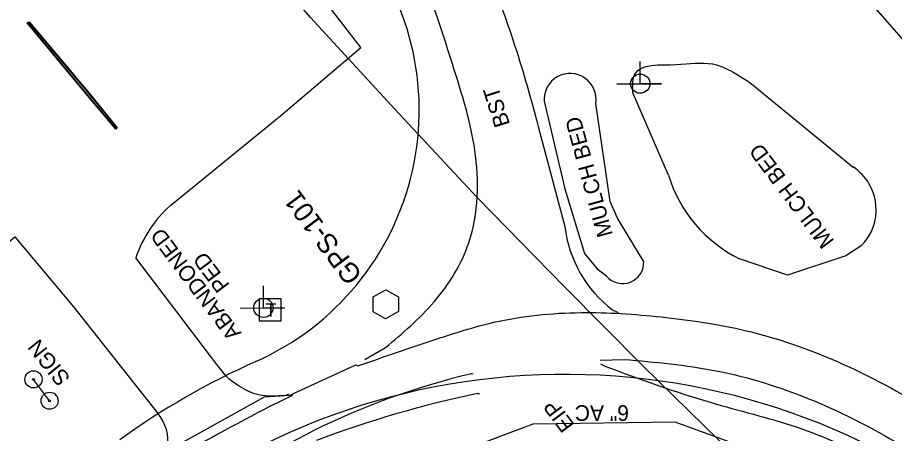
# Model space of a CAD drawing. Extents: x 1263837 to 1268319, y 770628 to 773628.
# Drawn here: x 1266190 to 1266413.1, y 772410.1 to 772515.9 of the extents above; entities that cross this region are included whole.
import ezdxf

# ---------------------------------------------------------------- set-up
doc = ezdxf.new("R2010")
doc.units = 0
for name, color, linetype in [('CTL Primary Horizontal and Vertical CELL', 7, 'Continuous'), ('CTL Primary Horizontal and Vertical Text', 7, 'Continuous'), ('Exist Other Culture Area Outline', 7, 'Continuous'), ('Exist Other Culture Area Outline Text', 7, 'Continuous'), ('Exist Other Culture Sign', 7, 'Continuous'), ('Exist Other Culture Sign Text', 7, 'Continuous'), ('Exist Property Iron Pin Text', 7, 'Continuous'), ('Exist Roads EOP Other', 7, 'Continuous'), ('Exist Roads EOP Text', 7, 'Continuous'), ('Exist Utilities Gas UG Line SUE LOS B', 7, 'Continuous'), ('Exist Utilities Power Joint Use Telephone CELL', 7, 'Continuous'), ('Exist Utilities Telephone Pedestal CELL', 7, 'Continuous'), ('Exist Utilities Telephone Pedestal Text', 7, 'Continuous'), ('Exist Utilities Water UG Line SUE LOS B', 7, 'Continuous'), ('Exist Utilities Water UG Line SUE LOS B Text', 7, 'Continuous'), ('Prop Horizontal Alignment', 7, 'Continuous'), ('Prop SS Fill Text', 7, 'Continuous'), ('Prop SS Transition Line', 7, 'Continuous'), ('Scratch_Level_2', 7, 'Continuous')]:
    doc.layers.add(name, color=color, linetype=linetype)

# ---------------------------------------------------------------- blocks, each defined once
blk = doc.blocks.new('EXIST UTILITIES POWER JOINT USE TELEPHONE')
at = {"layer": 'Exist Utilities Power Joint Use Telephone CELL'}
blk.add_line((0, 0), (0, 0), dxfattribs=at)
blk.add_lwpolyline([(-0.1188, 0), (0.108, -0.0008), (0, -0.0004), (0, 0.1125)], dxfattribs=at)
blk.add_circle((0, 0.0001), 0.049, dxfattribs=at)
blk = doc.blocks.new('EXIST UTILITIES TELEPHONE PEDESTAL')
at = {"layer": 'Exist Utilities Telephone Pedestal CELL'}
blk.add_line((0, 0), (0, 0), dxfattribs=at)
blk.add_lwpolyline([(-0.0545, -0.0565), (0.0574, -0.0565), (0.0574, 0.0554), (-0.0545, 0.0554), (-0.0545, -0.0565)], dxfattribs=at)
blk.add_text('T', height=0.0684, dxfattribs=at).set_placement((-0.0226, -0.0343))
blk = doc.blocks.new('CTL PRIMARY HORIZONTAL AND VERTICAL')
at = {"layer": 'CTL Primary Horizontal and Vertical CELL'}
blk.add_line((0, 0), (0, 0), dxfattribs=at)
blk.add_lwpolyline([(-0.0646, 0.0374), (0.0004, 0.0737), (0.0654, 0.0379), (0.0644, -0.0366), (-0.0006, -0.0743), (-0.0646, -0.0381)], close=True, dxfattribs=at)

msp = doc.modelspace()

# ---------------------------------------------------------------- linework, layer by layer
at = {"layer": 'Exist Other Culture Area Outline'}
for p, q in [((1266376.78, 772498.99), (1266402.61, 772477.85)), ((1266355.61, 772475.79), (1266346.58, 772496.72)), ((1266385.86, 772450.36), (1266373.65, 772454.51)), ((1266337.48, 772451.92), (1266339.86, 772450.14))]:
    msp.add_line(p, q, dxfattribs=at)
for points in [[(1266324.02, 772494.58), (1266329.26, 772472.26), (1266334.27, 772455.86), (1266337.48, 772451.92)], [(1266349.3, 772453.94), (1266342.64, 772464.83), (1266340.75, 772469.12), (1266337.12, 772493.99)], [(1266404.61, 772457.77), (1266400.71, 772455.26), (1266385.86, 772450.36)]]:
    msp.add_lwpolyline(points, dxfattribs=at)
for centre, major_axis, ratio, start_param, end_param in [((1266330.61, 772495.04), (-1.74, 6.39), 0.995965, 4.288081, 7.657894), ((1266395.46, 772467.08), (-10.22, 8.12), 0.990932, 3.017808, 4.796693), ((1266389.03, 772485.66), (26.79, -22.79), 0.986857, 4.139678, 4.955444), ((1266343.98, 772453.54), (4.6, -2.73), 0.999091, 4.368627, 6.893524)]:
    msp.add_ellipse(centre, major_axis=major_axis, ratio=ratio, start_param=start_param, end_param=end_param, dxfattribs=at)
msp.add_spline([(1266346.58, 772496.72), (1266347.13, 772501.58), (1266357.47, 772503.91), (1266366.8, 772504.06), (1266376.78, 772498.99)], degree=3, dxfattribs=at)
at = {"layer": 'Exist Other Culture Sign'}
msp.add_line((1266198.2, 772418.41), (1266194.11, 772423.85), dxfattribs=at)
for centre, radius in [((1266194.11, 772423.85), 2.18), ((1266194.11, 772423.85), 0.24), ((1266198.2, 772418.41), 2.18), ((1266198.2, 772418.41), 0.24)]:
    msp.add_circle(centre, radius, dxfattribs=at)
at = {"layer": 'Exist Roads EOP Other'}
msp.add_lwpolyline([(1266192.91, 772514.69), (1266207.85, 772496.92), (1266215.26, 772487.95), (1266215.01, 772487.7), (1266207.44, 772496.7), (1266192.76, 772514.42), (1266192.91, 772514.69)], dxfattribs=at)
at = {"layer": 'Exist Utilities Gas UG Line SUE LOS B'}
msp.add_lwpolyline([(1266634.89, 772116.41), (1266617.88, 772134.08), (1266593.74, 772162.87), (1266570.59, 772187.5), (1266552.2, 772208.93), (1266533.9, 772229.88), (1266520.79, 772243.67), (1266506.09, 772258.4), (1266476.3, 772293.88), (1266450.61, 772322.46), (1266432.17, 772342.72), (1266403.52, 772374.96), (1266376.24, 772400.79), (1266349.14, 772427.18), (1266329.27, 772447.31), (1266306.87, 772470.18), (1266286, 772492.58), (1266264.53, 772515.83), (1266241.63, 772542.64), (1266214.18, 772573.35), (1266190.07, 772598.41)], dxfattribs=at)
at = {"layer": 'Exist Utilities Water UG Line SUE LOS B'}
msp.add_lwpolyline([(1266813.73, 772072.54), (1266793.78, 772088.05), (1266755.27, 772103.69), (1266718.33, 772109.44), (1266678.54, 772111.01), (1266653.19, 772143.96), (1266605.92, 772197.31), (1266538.03, 772271.69), (1266479.88, 772335.62), (1266421.78, 772389.51), (1266357.3, 772412.97), (1266321.15, 772412.43), (1266255.77, 772387.79), (1266212.97, 772357.83), (1266212.08, 772352.35), (1266208.85, 772350.26), (1266194.96, 772350.29), (1266178.01, 772373.6), (1266155.19, 772357.9), (1266088.3, 772309.2), (1266057.71, 772286.98)], dxfattribs=at)
at = {"layer": 'Prop Horizontal Alignment'}
for centre, radius, start, end in [((1275094.23, 780056.99), 11329.16, 216.983333, 223.309327), ((1266222.23, 772492.36), 70, 293.9809, 40.4523), ((1266329.37, 772251.49), 193.62, 113.9809, 125.8167)]:
    msp.add_arc(centre, radius, start, end, dxfattribs=at)
at = {"layer": 'Prop SS Fill Text'}
for p, q in [((1266323.19, 772485.61), (1266329.27, 772462.71)), ((1266240.76, 772427.65), (1266220.16, 772454.78)), ((1266341.39, 772441.5), (1266342.84, 772440.85)), ((1266278.42, 772428.88), (1266283.64, 772431.92)), ((1266258.93, 772420.09), (1266258.29, 772419.74))]:
    msp.add_line(p, q, dxfattribs=at)
for points in [[(1266317.66, 772623.29), (1266342.19, 772594.53), (1266368.84, 772563.85), (1266396.95, 772531.19), (1266423.69, 772500.53), (1266451.34, 772469.08), (1266485.04, 772430.62), (1266513.92, 772398.56), (1266542.2, 772366.82), (1266568.73, 772337.14), (1266597.4, 772305.79), (1266627.45, 772273.2), (1266656.25, 772242.01), (1266683.72, 772211.17), (1266699.81, 772190.48)], [(1266229.02, 772468.13), (1266256.91, 772490.84), (1266277.4, 772508.24), (1266257.18, 772534.45), (1266234.23, 772562.55), (1266211.6, 772588.72), (1266200.28, 772601.91), (1266164.52, 772601.03), (1266130.88, 772600.07), (1266121.81, 772599.68), (1266117.21, 772604.39), (1266093.43, 772584.35), (1266064.08, 772559.94), (1266085.39, 772534.82), (1266055.13, 772509.93), (1266076.92, 772483.37), (1266101.03, 772454.47), (1266125.49, 772425.14), (1266134.49, 772414.39), (1266146.49, 772424.38), (1266164.67, 772402.08), (1266177.9, 772383.87)], [(1266193.03, 772514.81), (1266207.97, 772497.01), (1266215.43, 772487.83), (1266215.06, 772487.49), (1266207.41, 772496.55), (1266192.47, 772514.55), (1266193.03, 772514.81)], [(1266195.78, 772393.53), (1266179.19, 772413.75), (1266161.27, 772436.42), (1266189.4, 772460.06), (1266204.32, 772442.33), (1266225.79, 772415.07)], [(1266025.59, 772259.29), (1266057.53, 772282.19), (1266090.3, 772305.71), (1266122.01, 772329.02), (1266153.74, 772351.9), (1266173.76, 772367.02), (1266177.28, 772371.96), (1266201.03, 772388.23), (1266203.83, 772389.82), (1266209.58, 772391.53), (1266225.6, 772401.19), (1266228.25, 772405.78), (1266239.93, 772412.21), (1266252.84, 772419.39), (1266259.27, 772419.81), (1266276.13, 772427.55), (1266276.62, 772427.29)]]:
    msp.add_lwpolyline(points, dxfattribs=at)
for centre, major_axis, ratio, start_param, end_param in [((1266249.08, 772445.4), (-23.06, -20.17), 0.989359, 4.716732, 5.246147), ((1266360.21, 772466.33), (11.84, -28.83), 0.999192, 4.439519, 5.244611), ((1266217.62, 772408.14), (-2.22, 10.5), 0.997846, 4.356898, 5.205964)]:
    msp.add_ellipse(centre, major_axis=major_axis, ratio=ratio, start_param=start_param, end_param=end_param, dxfattribs=at)
for points in [[(1266283.64, 772431.92), (1266296, 772443.56), (1266304.82, 772458.59), (1266306.37, 772482.17), (1266301.46, 772501.55), (1266294.82, 772521.8), (1266286.96, 772543.15), (1266278.21, 772565.06), (1266268.13, 772588.22), (1266258.04, 772609.49), (1266248.62, 772628.93)], [(1266293.02, 772571.71), (1266302.33, 772547.85), (1266309.89, 772527.47), (1266317.36, 772506.16), (1266323.19, 772485.61)], [(1266276.62, 772427.29), (1266296.76, 772434.14), (1266312.57, 772438.66), (1266334.71, 772440.84), (1266354.99, 772439.59), (1266376.7, 772435.9), (1266400.18, 772427.65), (1266423.73, 772414.83), (1266442.53, 772401.44), (1266462.31, 772384.69), (1266479.28, 772369.15)], [(1266258.29, 772419.74), (1266251.4, 772419.91), (1266246.43, 772422.11), (1266243.49, 772424.3), (1266240.76, 772427.65)]]:
    msp.add_spline(points, degree=3, dxfattribs=at)
at = {"layer": 'Prop SS Transition Line'}
for p, q in [((1266338.25, 772428.75), (1266344.34, 772428.92)), ((1266338.34, 772427.8), (1266339.45, 772427.21)), ((1266305.53, 772425.28), (1266305.98, 772425.38)), ((1266307.01, 772420.27), (1266307.54, 772420.29)), ((1266254.5, 772417.08), (1266260.05, 772419.81)), ((1266242, 772398.73), (1266265.04, 772410.66))]:
    msp.add_line(p, q, dxfattribs=at)
for centre, major_axis, ratio, start_param, end_param in [((1266348.66, 772242.74), (-184.27, -36.54), 0.998447, 4.748618, 4.978285), ((1266365.99, 772144.29), (-279.74, -54.24), 0.990401, 4.731257, 4.881131), ((1266563.65, 771819.18), (-666.75, 95.8), 0.99888, 5.331757, 5.377079)]:
    msp.add_ellipse(centre, major_axis=major_axis, ratio=ratio, start_param=start_param, end_param=end_param, dxfattribs=at)
for points in [[(1266339.45, 772427.21), (1266366.25, 772418.02), (1266388.1, 772411.74), (1266410.05, 772401.92), (1266429.01, 772389.72), (1266448.51, 772374.07), (1266467.93, 772354.23)], [(1266344.34, 772428.92), (1266367.71, 772426.04), (1266391.52, 772418.84), (1266413.16, 772408.02), (1266432.74, 772394.53), (1266452.23, 772378.67), (1266472.87, 772359.23)]]:
    msp.add_spline(points, degree=3, dxfattribs=at)
at = {"layer": 'Scratch_Level_2'}
for centre, radius, start, end in [((1275094.23, 780056.99), 11459.16, 216.983333, 225.433333), ((1266329.37, 772251.49), 173.62, 43.2333, 125.8167)]:
    msp.add_arc(centre, radius, start, end, dxfattribs=at)

# ---------------------------------------------------------------- block references
at = {"layer": 'CTL Primary Horizontal and Vertical CELL', "xscale": 50, "yscale": 50}
msp.add_blockref('CTL PRIMARY HORIZONTAL AND VERTICAL', (1266283.71, 772442.95), dxfattribs=at)
msp.add_blockref('CTL PRIMARY HORIZONTAL AND VERTICAL', (1266283.71, 772442.95), dxfattribs=at)
at = {"layer": 'Exist Utilities Power Joint Use Telephone CELL', "xscale": 50, "yscale": 50}
for p in [(1266348.44, 772499.04), (1266252.59, 772442.03)]:
    msp.add_blockref('EXIST UTILITIES POWER JOINT USE TELEPHONE', p, dxfattribs=at)
at = {"layer": 'Exist Utilities Telephone Pedestal CELL', "xscale": 50, "yscale": 50}
msp.add_blockref('EXIST UTILITIES TELEPHONE PEDESTAL', (1266254.23, 772441.52), dxfattribs=at)

# ---------------------------------------------------------------- texts
at = {"layer": 'CTL Primary Horizontal and Vertical Text'}
msp.add_text('GPS-101', height=5, rotation=126.9057, dxfattribs=at).set_placement((1266277.98, 772450.37))
at = {"layer": 'Exist Other Culture Area Outline Text'}
for rotation, p in [(105.4346, (1266341.5, 772460.65)), (126.9057, (1266397.95, 772459.05))]:
    msp.add_text('MULCH BED', height=4, rotation=rotation, dxfattribs=at).set_placement(p)
at = {"layer": 'Exist Other Culture Sign Text'}
msp.add_text('SIGN', height=4, rotation=128.622, dxfattribs=at).set_placement((1266203.66, 772424.22))
at = {"layer": 'Exist Property Iron Pin Text'}
msp.add_text('EIP', height=4, rotation=126.9057, dxfattribs=at).set_placement((1266331.9, 772412.29))
at = {"layer": 'Exist Roads EOP Text'}
msp.add_text('BST', height=4, rotation=107.6779, dxfattribs=at).set_placement((1266315.36, 772488.72))
at = {"layer": 'Exist Utilities Telephone Pedestal Text'}
for s, p in [('ABANDONED', (1266247.11, 772435.62)), ('PED', (1266244.19, 772447.84))]:
    msp.add_text(s, height=4, rotation=126.9057, dxfattribs=at).set_placement(p)
at = {"layer": 'Exist Utilities Water UG Line SUE LOS B Text'}
msp.add_text('6" AC', height=4, rotation=179.9882, dxfattribs=at).set_placement((1266345.58, 772417.28))

doc.saveas('drawing.dxf')
